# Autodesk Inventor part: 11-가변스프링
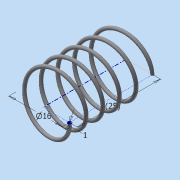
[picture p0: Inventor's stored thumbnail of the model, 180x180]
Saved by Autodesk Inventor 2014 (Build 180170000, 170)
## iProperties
Created: 2015-06
Part Number: 11-가변스프링
Material: 강철, 연강
Document SubType Name: Modeling
Designer: Administrator
Density: 7.86 g/cm^3
Appearance: 강철
Mass: 1.53479 g
Surface Area: 7.89194 cm^2
Volume: 0.195266 cm^3
Author: Administrator
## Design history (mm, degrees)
sketch "스케치1"
  geometry: L1 (0, 0)-(8, 0); L2 (8, 0)-(8, 21.5); L3 (8, 21.5)-(0, 21.5); L4 (0, 21.5)-(0, 0); C1 r 0.5 at (8, 0)
  constraints: 8 end point, 2 parallel, 1 centre point, 1 coincident, 1 horizontal, 1 perpendicular
  dimensions: "d0" = 1 diameter of C1; "d1" = 16 diameter of L2 L4; "d2" = 21.5 distance of L1.end L2.end (derived)
feature "코일1" sketch "스케치1" pitch "d3" = 10; turns "d5" = 5; dims "d4" = 21.5 (= d2), "d6" = 0, angle "d7" = 90 deg, angle "d8" = 90 deg, "d9" = 0, "d10" = 0
sketch "스케치2"
  geometry: L1 (-8.5, 0)-(-7.5, 0) reference; 1 further point
  constraints: 1 horizontal alignment
extrude "돌출1" cut sketch "스케치2" distance "d11" = 10; taper "d12" = 0 deg
node "작업 평면1"
sketch "스케치3"
  geometry: L1 (-7.5, 0)-(-8.5, 0) reference; 1 further point
  constraints: 1 horizontal alignment
extrude "돌출2" cut sketch "스케치3" distance "d14" = 10; taper "d15" = 0 deg
node "솔리드1"
node "절단 모서리 투영1"
node "절단 모서리 투영2"
other parameters: "d13" = 21.5 (= d2)
